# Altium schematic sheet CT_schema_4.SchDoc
size 310 x 315 mm
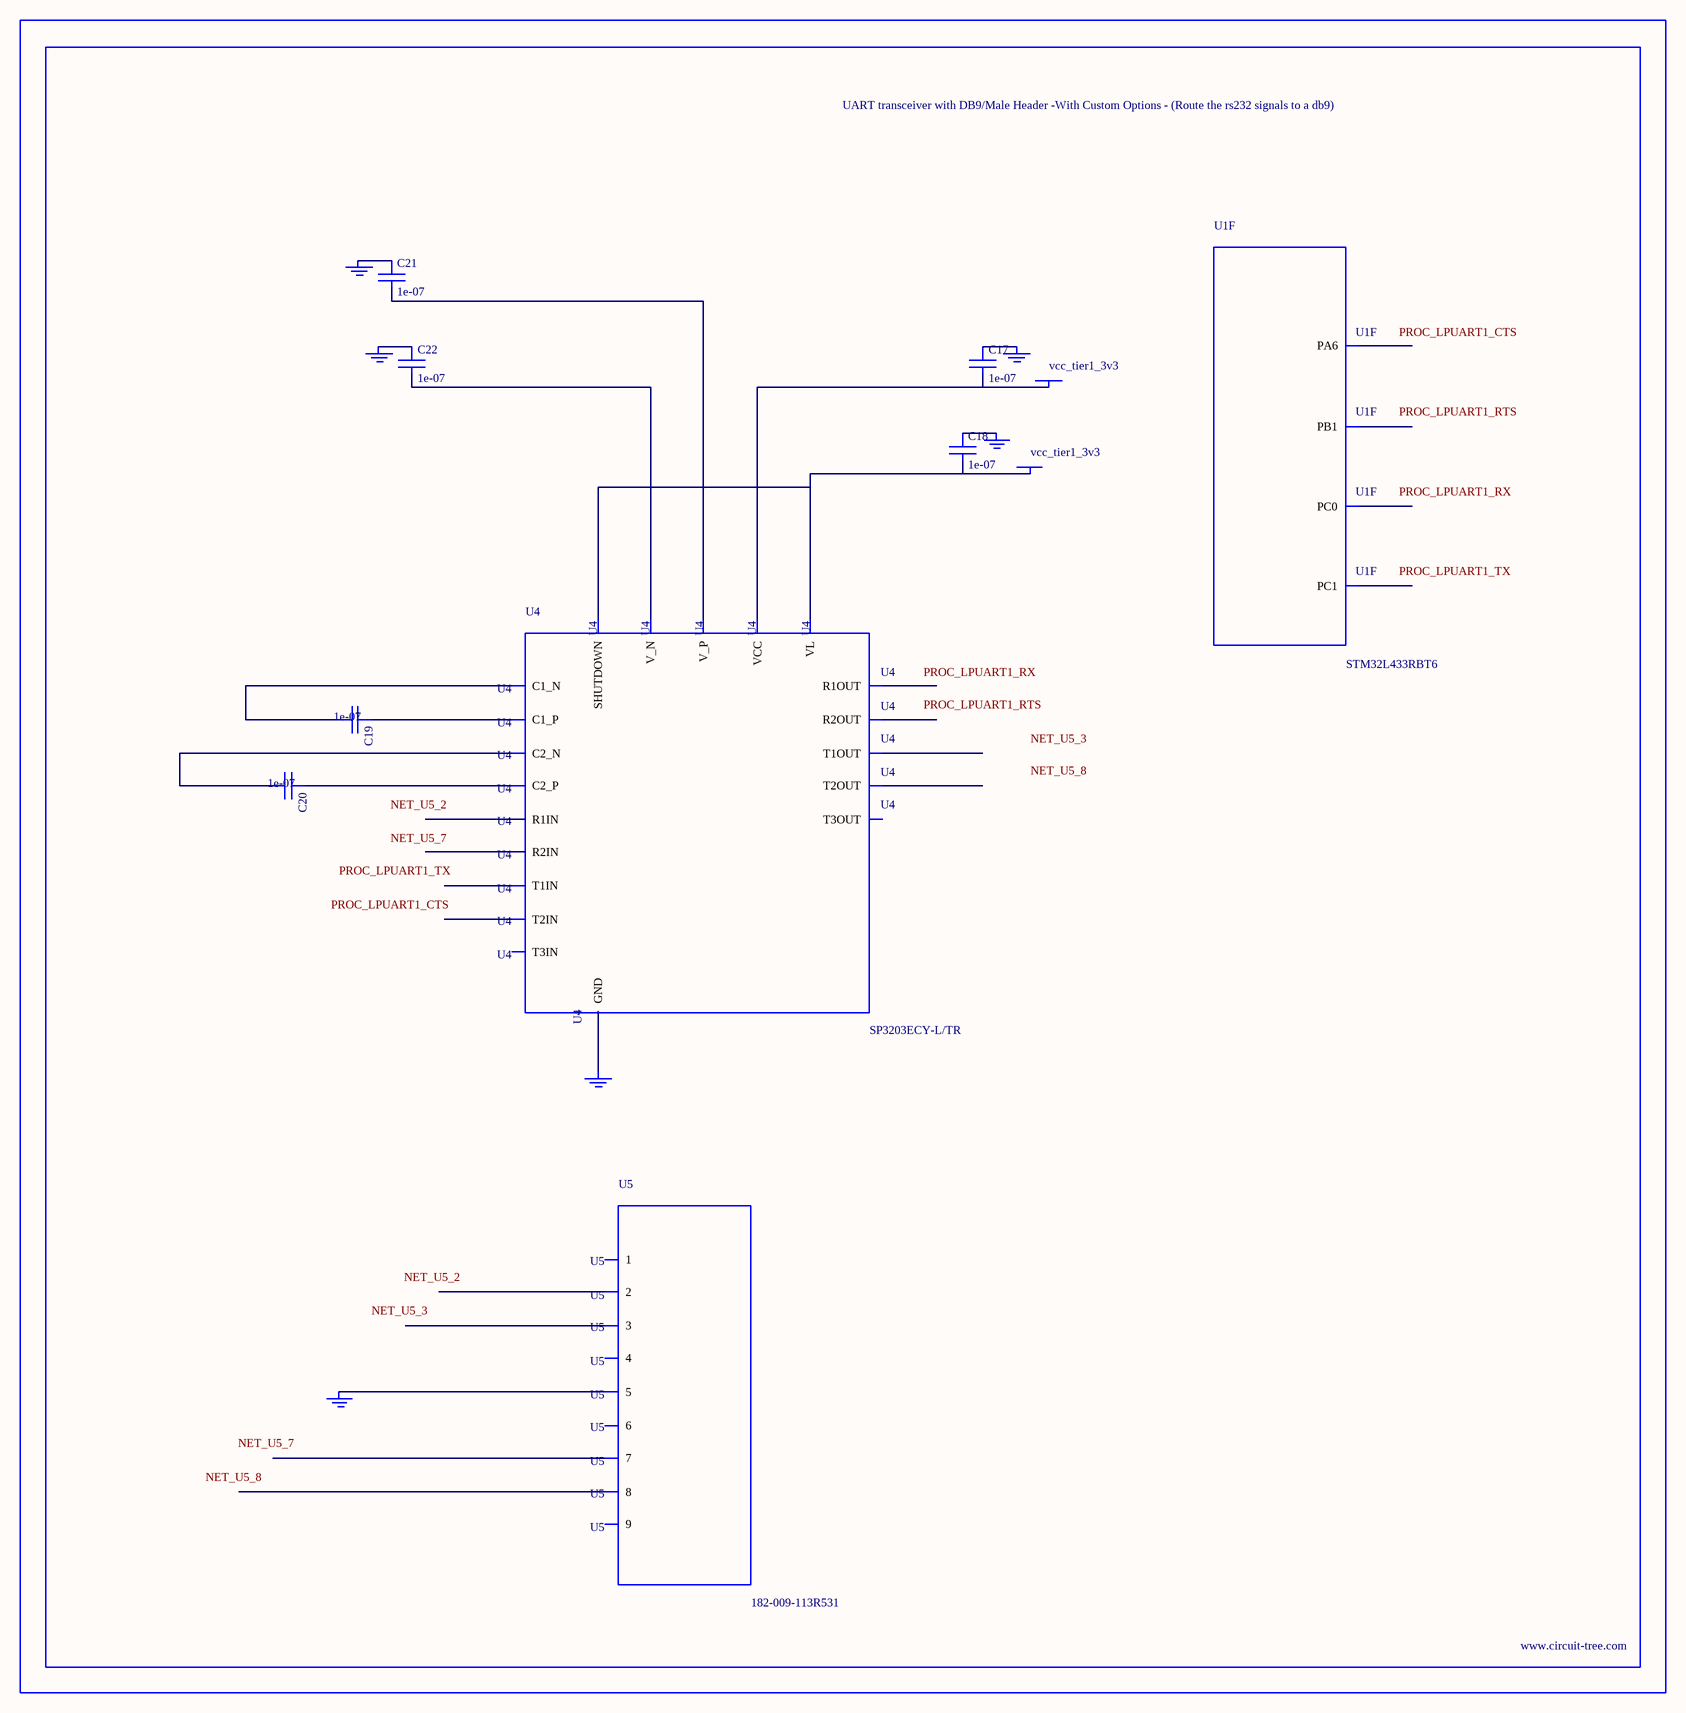
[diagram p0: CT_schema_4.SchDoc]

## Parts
BORDER3  (no value)
C17  1e-07  [C0402]
C18  1e-07  [C0402]
C19  1e-07  [C0402]
C20  1e-07  [C0402]
C21  1e-07  [C0402]
C22  1e-07  [C0402]
GND_INSTANCE_3_0  (no value)
GND_INSTANCE_3_1  (no value)
GND_INSTANCE_3_2  (no value)
GND_INSTANCE_3_3  (no value)
GND_INSTANCE_3_4  (no value)
GND_INSTANCE_3_5  (no value)
POWER_INSTANCE_3_0  vcc_tier1_3v3
POWER_INSTANCE_3_1  vcc_tier1_3v3
U1  STM32L433RBT6  [LQFP64]  (part F of 7)
U4  SP3203ECY-L/TR  [TSSOP20-I]
U5  182-009-113R531  [182-009-MALE]

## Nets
NetC17_1: C17.1 GND_INSTANCE_3_3.0(GND)
NetC17_2: C17.2 POWER_INSTANCE_3_1.0(PWR) U4.19(VCC)
NetC18_1: C18.1 GND_INSTANCE_3_2.0(GND)
NetC18_2: C18.2 POWER_INSTANCE_3_0.0(PWR) U4.12(VL) U4.20(SHUTDOWN)
NetC19_1: C19.1 U4.1(C1_P)
NetC19_2: C19.2 U4.3(C1_N)
NetC20_1: C20.1 U4.4(C2_P)
NetC20_2: C20.2 U4.5(C2_N)
NetC21_1: C21.1 GND_INSTANCE_3_0.0(GND)
NetC21_2: C21.2 U4.2(V_P)
NetC22_1: C22.1 GND_INSTANCE_3_1.0(GND)
NetC22_2: C22.2 U4.6(V_N)
NetGND_INSTANCE_3_4_0: GND_INSTANCE_3_4.0(GND) U4.18(GND)
NetGND_INSTANCE_3_5_0: GND_INSTANCE_3_5.0(GND) U5.5

Not connected (* = marked no-connect by the designer): U1 8(PC0) 9(PC1) 22(PA6) 27(PB1); U4 7(T1IN) 8(T2IN) 9(T3IN) 10(R2OUT) 11(R1OUT) 13(R2IN) 14(R1IN) 15(T3OUT) 16(T2OUT) 17(T1OUT); U5 1 2 3 4 6 7 8 9

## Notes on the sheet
- Labels drawn without touching a wire or pin: NET_U5_2, NET_U5_3, NET_U5_7, NET_U5_8, PROC_LPUART1_CTS, PROC_LPUART1_RTS, PROC_LPUART1_RX, PROC_LPUART1_TX

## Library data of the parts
BORDER3 = BORDER_PAGE3
C17-C22 = C0402C104K3RACTU
GND_INSTANCE_3_0-GND_INSTANCE_3_5 = GND
POWER_INSTANCE_3_0 POWER_INSTANCE_3_1 = PWR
